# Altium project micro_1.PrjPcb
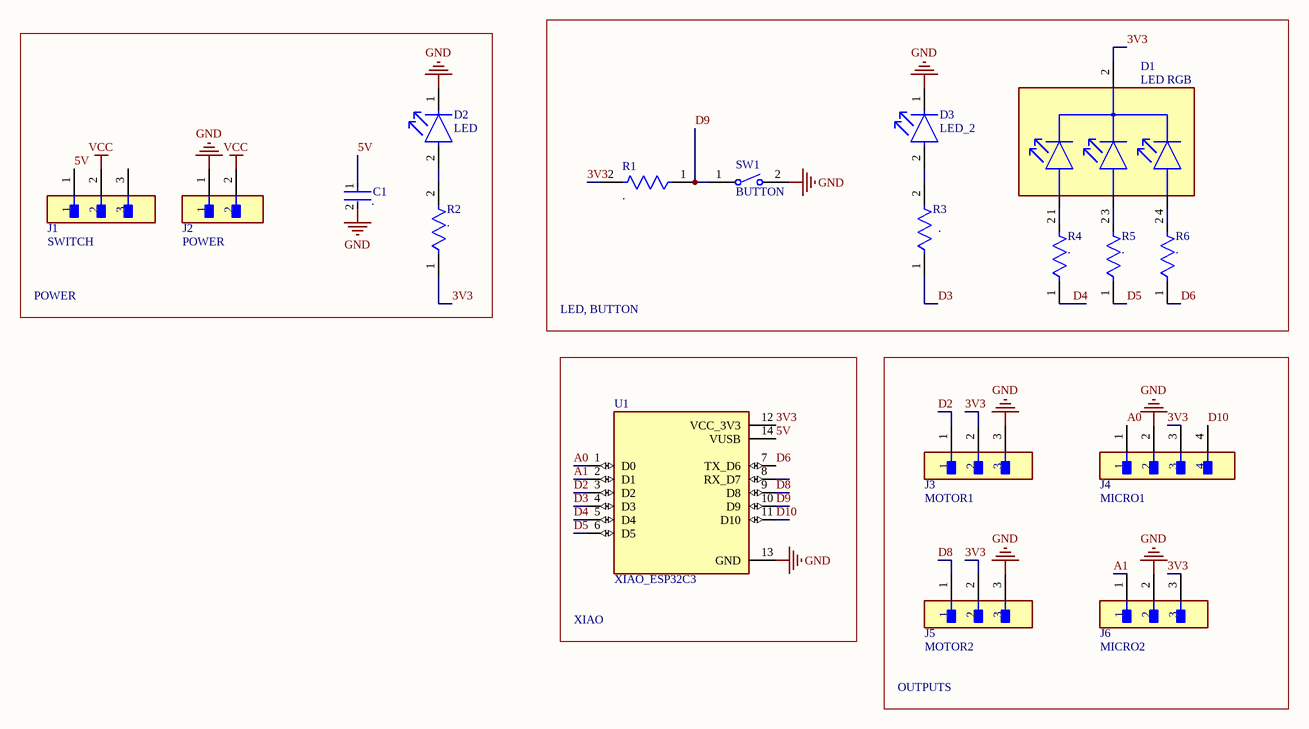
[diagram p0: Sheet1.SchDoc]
1 sheet, 18 parts. Net scope: global (net labels, ports and power ports of the same name join across sheets).
Board file: PCB6.PcbDoc

## Sheet Sheet1.SchDoc
size A4; SheetNumber: 1; SheetTotal: 1

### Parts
C1  .  [FP-C1206C-EB-MFG]
D1  LED RGB  [FP-AAA3528LSEKJ3ZGKQBKS-MFG]
D2  LED  [FP-LTST-C150KSKT-MFG]
D3  LED_2  [FP-LTST-C150KSKT-MFG]
J1  SWITCH  [FP-PR20203VBNN-MFG]
J2  POWER  [FP-TSW-102-12-T-S-MFG]
J3  MOTOR1  [FP-PR20203VBNN-MFG]
J4  MICRO1  [FP-TSW-104-22-G-S-MFG]
J5  MOTOR2  [FP-PR20203VBNN-MFG]
J6  MICRO2  [FP-PR20203VBNN-MFG]
R1  .  [FP-AC1206-MFG]
R2  .  [FP-AC1206-MFG]
R3  .  [FP-AC1206-MFG]
R4  .  [FP-AC1206-MFG]
R5  .  [FP-AC1206-MFG]
R6  .  [FP-AC1206-MFG]
SW1  BUTTON  [TECO-FSMSM-2_V]
U1  XIAO_ESP32C3  [MODULE_XIAO_ESP32C3]

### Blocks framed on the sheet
POWER: C1 D2 J1 J2 R2
LED, BUTTON: D1 D3 R1 R3-R6 SW1
XIAO: U1
OUTPUTS: J3-J6

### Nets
GND: C1.2 D2.1(C) D3.1(C) J2.1 J3.3 J4.2 J5.3 J6.2 SW1.2 U1.13(GND)
VCC: J1.2 J2.2
3V3: D1.2(COMMON_CATHODE) J3.2 J4.3 J5.2 J6.3 R1.2 R2.1 U1.12(VCC_3V3)
5V: C1.1 J1.1 U1.14(VUSB)
A0: J4.1 U1.1(D0)
A1: J6.1 U1.2(D1)
D2: J3.1 U1.3(D2)
D3: R3.1 U1.4(D3)
D4: R4.1 U1.5(D4)
D5: R5.1 U1.6(D5)
D6: R6.1 U1.7(TX_D6)
D8: J5.1 U1.9(D8)
D9: R1.1 SW1.1 U1.10(D9)
D10: J4.4 U1.11(D10)
NetD1_1: D1.1(ANODE_RED) R4.2
NetD1_3: D1.3(ANODE_GREEN) R5.2
NetD1_4: D1.4(ANODE_BLUE) R6.2
NetD2_2: D2.2(A) R2.2
NetD3_2: D3.2(A) R3.2

Not connected (* = marked no-connect by the designer): J1 3; U1 8(RX_D7)

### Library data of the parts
C1 = CMP-03020-023751-1: C1206 100 pF X8R 10.00% 50 V; Manufacturer: KEMET; Manufacturer Part Number: C1206C101K5HACTU; Capacitance: 100 pF; Temperature Coefficient: 15%; Voltage Rating: 50 V; Tolerance: 0.1; Automotive Grade: Grade 0; Value: 100 pF; Material: Ceramic
D1 = CMP-44529-000057-1: LED RGB CLEAR 4SMD; Forward Voltage: 2.7V; Lens Color: Colorless; Luminous Intensity: 30mcd; Viewing Angle: 120°; Color: Blue; Test Current: 2mA; Dominant Wavelength: 465nm
D2 D3 = CMP-2000-06618-2: LED YELLOW CLEAR 1206 SMD; Power Rating: 75mW; Wavelength: 588nm; Forward Current: 30mA; Test Current: 20mA; Viewing Angle: 130°; Forward Voltage: 2.4V; Luminous Intensity: 60mcd; Lens Style: Diffused; Number of Elements: 1; Reverse Voltage: 5V; Lens Color: Colorless; Dominant Wavelength: 587nm
J1 J3 J5 J6 = CMP-77940-000002-1: CONN HEADER VERT 3POS 2.54MM; Manufacturer Part Number: PR20203VBNN; Manufacturer: Metz Connect; Conn Orientation: Straight; Current Rating: 3A; Number Of Contacts: 3; Conn Gender: Male
J2 = CMP-02766-001444-1: CONN HEADER VERT 2POS 2.54MM; Gender: Male; Number of Contacts: 2
J4 = CMP-02766-001236-1: CONN HEADER VERT 4POS 2.54MM; Number of Contacts: 4; Gender: Male
R1-R6 = CMP-03412-032679-1: RES SMD 2.21K OHM 1% 1/4W 1206; Manufacturer: Yageo; Manufacturer Part Number: AC1206FR-072K21L; Automotive Grade: Grade 0; Voltage Rating: 200V; Tolerance: 0.01; Value: 2.21KΩ; Power Rating: 0.25W
SW1 = CMP-2000-07511-1: FSMSM Push Button Switch, 50 mA, -35 to 85 degC, 2-Pin SMD, RoHS, Bulk; Manufacturer: TE Connectivity; Actuator Length: 1.07mm; Electrical Life: 20000Cycles; Actuator Material: Polyamide; Current Rating: 50mA; Illumination Type: Illuminated; Voltage Rating (DC): 24V; Contact Resistance: 100mOhm; Case\/Package: SMD/SMT; Operating Force: 180gf; Switch Travel: 0.25mm; Max Voltage Rating (DC): 12V; Throw Configuration: SPST
U1 = XIAO_ESP32C3: Dev.kit: evaluation; u.FL antenna,prototype board; XIAO; PIN: 2x7; MF: Seeed Studio; MP: XIAO ESP32C3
